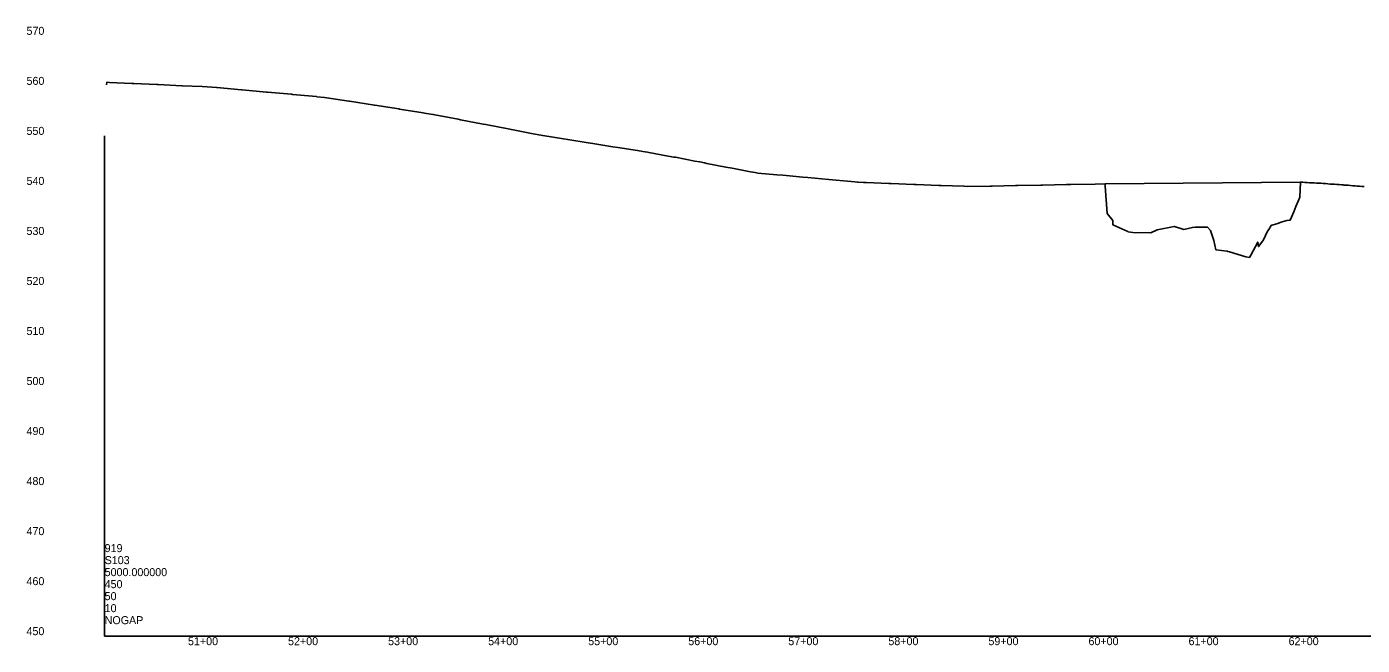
# Model space of a CAD drawing. Extents: x 49922 to 52614, y 49991 to 60509.
# Drawn here: x 49922 to 51257, y 49991 to 50609 of the extents above; entities that cross this region are included whole.
import ezdxf

# ---------------------------------------------------------------- set-up
doc = ezdxf.new("R2010")
doc.units = 0
for name, color, linetype in [('RD_DDB_ElevTX', 7, 'Continuous'), ('RD_DDB_Profile_EX', 7, 'Continuous'), ('RD_DDB_StaTX', 7, 'Continuous'), ('RD_GPK_Profile_Cell', 7, 'Continuous')]:
    doc.layers.add(name, color=color, linetype=linetype)

msp = doc.modelspace()

# ---------------------------------------------------------------- linework, layer by layer
at = {"layer": 'RD_DDB_Profile_EX'}
msp.add_line((51000, 50452.2), (51195.2, 50453.8), dxfattribs=at)
for points in [[(50002, 50551), (50002.3, 50553.6), (50004.7, 50553.4), (50027.3, 50552.4), (50029.1, 50552.3), (50052.3, 50551.3), (50053.5, 50551.2), (50077.3, 50550.1), (50077.9, 50550.1), (50097.5, 50549.2), (50102.4, 50548.9), (50111.8, 50548.4), (50112.2, 50548.4), (50136.8, 50546.1), (50137.4, 50546.1), (50161.8, 50543.8), (50162.6, 50543.8), (50186.8, 50541.6), (50187.8, 50541.5), (50211.8, 50539.3), (50212.2, 50539.2), (50219.7, 50538.5), (50244, 50534.8), (50244.7, 50534.6), (50269.7, 50530.8), (50270, 50530.7), (50294, 50526.9), (50294.7, 50526.8), (50318.3, 50523.1), (50319.7, 50522.8), (50327.9, 50521.5), (50328.4, 50521.5), (50330.1, 50521.1), (50353.4, 50516.6), (50355.6, 50516.2), (50378.4, 50511.8), (50381.1, 50511.3), (50403.4, 50507), (50406.5, 50506.3), (50428.3, 50502.1), (50436.1, 50500.6), (50437.8, 50500.3), (50458.6, 50497), (50462.8, 50496.3), (50483.3, 50493.1), (50487.8, 50492.4), (50507.9, 50489.2), (50512.8, 50488.4), (50532.6, 50485.3), (50537.8, 50484.5), (50542.7, 50483.7), (50543.8, 50483.5), (50563.1, 50479.8), (50568.8, 50478.9), (50570.5, 50478.6), (50589.8, 50474.9), (50594.8, 50474), (50599.4, 50473.2), (50602, 50472.4), (50620.7, 50468.8), (50627.1, 50467.7), (50645.5, 50464.2), (50650.2, 50463.4), (50652.7, 50462.9), (50671.7, 50461.2), (50677.7, 50460.6), (50697.7, 50458.9), (50702.7, 50458.4), (50723.7, 50456.5), (50727.6, 50456.2), (50749.8, 50454.2), (50752.6, 50453.9), (50753, 50453.9), (50758.6, 50453.4), (50761, 50453.3), (50783.6, 50452.4), (50786, 50452.4), (50808.6, 50451.5), (50811.1, 50451.4), (50833.6, 50450.5), (50836.1, 50450.5), (50858.6, 50449.6), (50859.1, 50449.6), (50862.2, 50449.5), (50885.1, 50449.9), (50887.2, 50449.9), (50910.5, 50450.4), (50912.2, 50450.4), (50935.8, 50450.8), (50937.2, 50450.9), (50961.2, 50451.3), (50962.2, 50451.3), (50964.8, 50451.4), (50965.7, 50451.4), (50990, 50451.9), (51000, 50452.2), (51000.1, 50449.8), (51002.1, 50422.3), (51007.6, 50415.5), (51007.8, 50411.2), (51022.6, 50404.5)], [(51022.6, 50404.5), (51023.1, 50404.2), (51027.7, 50403.5), (51045.5, 50403.2), (51051.8, 50406), (51068.9, 50409.4), (51069.3, 50409.4), (51078.6, 50406.6), (51087.1, 50408.6), (51090, 50408.7), (51101.6, 50408.8), (51102.2, 50408.9), (51105.4, 50405.3), (51108.5, 50395.5), (51110.7, 50386.2), (51121.9, 50384.7), (51122.7, 50384.6), (51124.3, 50384.1), (51140.4, 50379), (51144.1, 50378.6), (51145.6, 50380.9), (51152.5, 50393.9), (51153.1, 50389.4), (51157.4, 50395.2), (51158.3, 50396.2), (51162.3, 50404.8), (51163.4, 50406.6), (51166, 50410.6), (51166.7, 50410.8), (51168, 50411.2), (51170.2, 50411.9), (51172.5, 50412.6), (51174.8, 50413.3), (51177, 50414), (51179.3, 50414.7), (51181.6, 50415.3), (51183.9, 50415.7), (51184.9, 50415.8), (51186.1, 50418.7), (51188.4, 50424.1), (51190.7, 50429.5), (51192.9, 50434.9), (51194.5, 50438.7), (51195.2, 50453.8), (51197.5, 50453.6), (51199.7, 50453.5), (51202, 50453.4), (51204.3, 50453.2), (51206.6, 50453.1), (51208.8, 50453), (51211.1, 50452.8), (51213.4, 50452.7), (51215.6, 50452.6), (51217.9, 50452.4), (51219.3, 50452.3), (51220.2, 50452.3), (51222.4, 50452.1), (51224.7, 50451.9), (51227, 50451.8), (51229.3, 50451.6), (51231.5, 50451.5), (51233.8, 50451.3), (51236.1, 50451.1), (51238.3, 50451), (51238.6, 50450.9), (51240.6, 50450.7), (51242.9, 50450.6), (51245.1, 50450.4), (51247.4, 50450.2), (51249.7, 50450.1), (51252, 50449.9), (51254.2, 50449.7), (51256.5, 50449.5), (51258.8, 50449.4)]]:
    msp.add_lwpolyline(points, dxfattribs=at)
at = {"layer": 'RD_GPK_Profile_Cell'}
for q in [(50000, 50500), (52600, 50000), (50000, 50000)]:
    msp.add_line((50000, 50000), q, dxfattribs=at)

# ---------------------------------------------------------------- texts
at = {"layer": 'RD_DDB_ElevTX'}
for s, p in [('570', (49921.9, 50601)), ('560', (49921.9, 50551)), ('550', (49921.9, 50501)), ('540', (49921.9, 50451)), ('530', (49921.9, 50401)), ('520', (49921.9, 50351)), ('510', (49921.9, 50301)), ('500', (49921.9, 50251)), ('490', (49921.9, 50201)), ('480', (49921.9, 50151)), ('470', (49921.9, 50101)), ('460', (49921.9, 50051)), ('450', (49921.9, 50001))]:
    msp.add_text(s, height=8, dxfattribs=at).set_placement(p)
at = {"layer": 'RD_DDB_StaTX'}
for s, p in [('51+00', (50083.3, 49991)), ('52+00', (50183.3, 49991)), ('53+00', (50283.3, 49991)), ('54+00', (50383.3, 49991)), ('55+00', (50483.3, 49991)), ('56+00', (50583.3, 49991)), ('57+00', (50683.3, 49991)), ('58+00', (50783.3, 49991)), ('59+00', (50883.3, 49991)), ('60+00', (50983.3, 49991)), ('61+00', (51083.3, 49991)), ('62+00', (51183.3, 49991))]:
    msp.add_text(s, height=8, dxfattribs=at).set_placement(p)
at = {"layer": 'RD_GPK_Profile_Cell'}
for s, p in [('919', (50000, 50084)), ('S103', (50000, 50072)), ('5000.000000', (50000, 50060)), ('450', (50000, 50048)), ('50', (50000, 50036)), ('10', (50000, 50024)), ('NOGAP', (50000, 50012))]:
    msp.add_text(s, height=8, dxfattribs=at).set_placement(p)

doc.saveas('drawing.dxf')
